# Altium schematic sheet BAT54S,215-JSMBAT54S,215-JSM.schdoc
size 127 x 101 mm
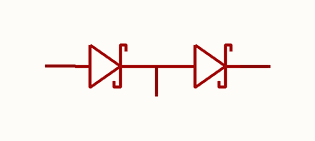
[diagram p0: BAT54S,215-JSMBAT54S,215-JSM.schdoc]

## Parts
D?  bat54s,215-jsm  [SOT-23-3_L2.9-W1.3-P1.90-LS2.4-BL-2]  (value not drawn)

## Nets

Not connected (* = marked no-connect by the designer): D? 1(A) 2(K) 3

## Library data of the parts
D? = bat54s,215-jsm: 二极管配置:1对串联式;正向压降(Vf):800mV@100mA;直流反向耐压(Vr):30V;整流电流:200mA;; Manufacturer: JSMSEMI(杰盛微); AddInBom: yes; ModelId: 115ef394a879442d90491e6127930138; ModelName: SOT-23-3_L2.9-W1.3-P1.90-LS2.4; ModelTransform: 114.173,94.488,0,0,0,0,0,0,0; Diode Configuration: 1对串联式; Voltage - DC Reverse(Vr): 30V; Current - Rectified: 200mA; Reverse Leakage Current (Ir): 2uA@25V; Non-Repetitive Peak Forward Surge Current: 600mA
